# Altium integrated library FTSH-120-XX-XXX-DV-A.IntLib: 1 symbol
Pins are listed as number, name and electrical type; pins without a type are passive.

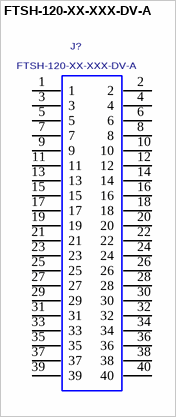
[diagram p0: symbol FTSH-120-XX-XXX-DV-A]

## FTSH-120-XX-XXX-DV-A
designator J?
0.050 INCH DOUBLE VERTICAL SMT TERMINAL STIP.; MANUFACTURER: SAMTEC
footprint FTSH-120-XX-XXX-DV-A
pins: 1, 2, 3, 4, 5, 6, 7, 8, 9, 10, 11, 12, 13, 14, 15, 16, 17, 18, 19, 20, 21, 22, 23, 24, 25, 26, 27, 28, 29, 30, 31, 32, 33, 34, 35, 36, 37, 38, 39, 40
